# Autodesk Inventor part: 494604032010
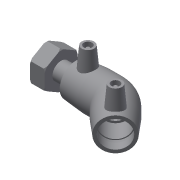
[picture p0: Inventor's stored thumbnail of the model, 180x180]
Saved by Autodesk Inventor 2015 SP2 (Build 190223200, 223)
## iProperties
Created: 2017-06
Part Number: 494604032010
Material: Generic
Description: PLASSON 45° ELBOW FEMALE FREE NUT TRANSITION 32-1"
Document SubType Name: Modeling
Designer: KIM
Mass: 55.0731 g
Surface Area: 148.067 cm^2
Volume: 55.0731 cm^3
Density: 1 g/cm^3
Appearance: Default
Author: KIM
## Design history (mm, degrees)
derived "494604.ipt"
feature "Solid1::494604.ipt"
tag "TaggingFeature1"
body "Solid1"
other parameters: "d2" = 44, "d4" = 23.75, "d5" = 39.6, "d8" = 168 deg, "d10" = 15.6, "d11" = 5.2, "d29" = 43, "d30" = 15, "d31" = 33.25, "d34" = 5 deg, "d41" = 4, "d42" = 14, "d43" = 0, "d49" = 32, "d50" = 27.2, "d51" = 15.6, "d52" = 39.39, "d54" = 135 deg, "d86" = 19.8, "d87" = 135 deg, "d88" = 95, "d90" = 39, "d91" = 0, "d92" = 39, "d93" = 0, "d101" = 3, "d102" = 0, "d108" = 19, "d110" = 36, "d112" = 45.4365, "d113" = 30.291, "d139" = 21.2037, "d140" = 19, "d141" = 18, "d142" = 1.8, "d143" = 3.6, "d144" = 14.4, "d145" = 24.2328, "d146" = 1.51455, "d150" = 0, "d151" = 1.6, "d_" = 32, "L_" = 131, "L_1" = 39, "D_" = 19, "A_" = 43, "d_2" = 12, "L_2" = 36, "G_" = 30.291, "D_1" = 44
